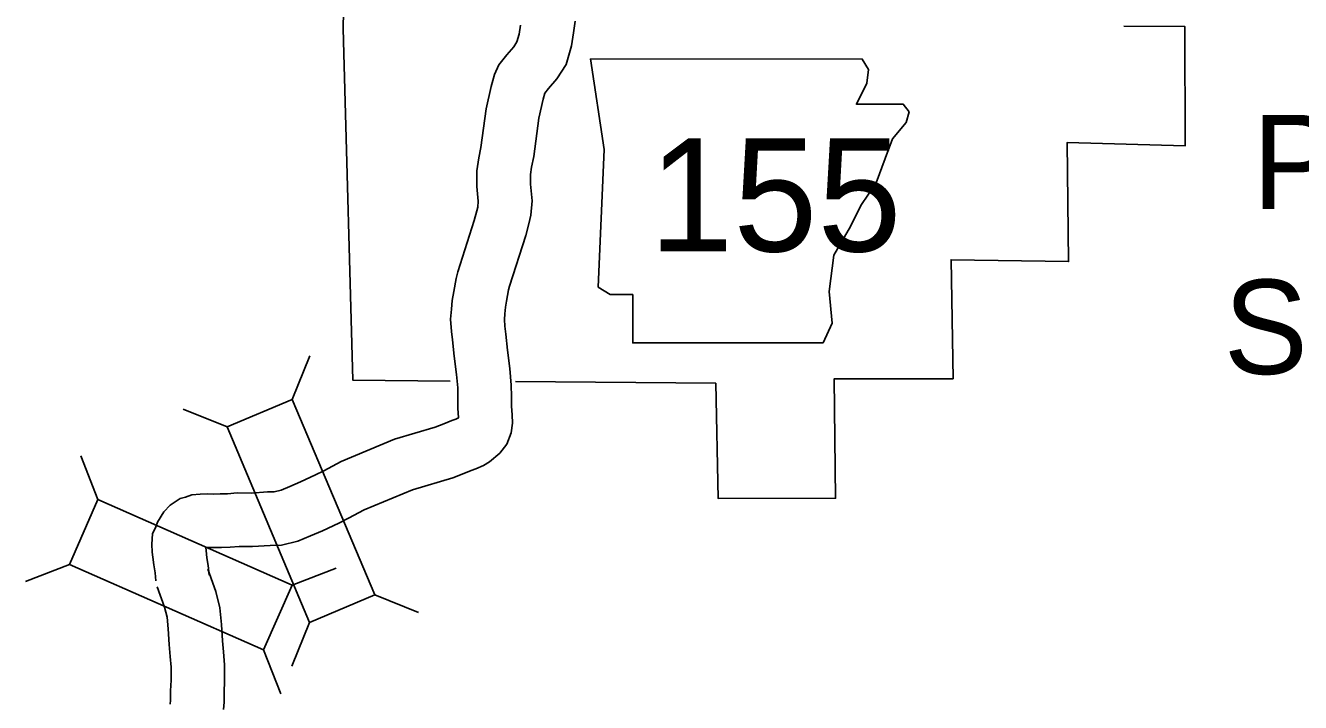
# Model space of a CAD drawing. Extents: x 1374139 to 1377472, y 1168351 to 1170484.
# Drawn here: x 1374780.3 to 1374851.7, y 1169701.5 to 1169739.4 of the extents above; entities that cross this region are included whole.
import ezdxf

# ---------------------------------------------------------------- set-up
doc = ezdxf.new("R2010")
doc.units = 0
doc.layers.add('Default', color=7, linetype='Continuous')

msp = doc.modelspace()

# ---------------------------------------------------------------- linework, layer by layer
at = {"layer": 'Default'}
for p, q in [((1374795.273, 1169718.442), (1374796.267, 1169720.888)), ((1374791.625, 1169716.902), (1374789.179, 1169717.896)), ((1374784.399, 1169712.832), (1374783.443, 1169715.293)), ((1374782.803, 1169709.208), (1374780.342, 1169708.252)), ((1374795.271, 1169708.045), (1374797.732, 1169709.001)), ((1374799.894, 1169707.498), (1374802.34, 1169706.504)), ((1374796.246, 1169705.958), (1374795.252, 1169703.512)), ((1374793.676, 1169704.421), (1374794.632, 1169701.96))]:
    msp.add_line(p, q, dxfattribs=at)
for points in [[(1374804.127, 1169719.47), (1374798.677, 1169719.513), (1374798.163, 1169737.81), (1374798.134, 1169739.222), (1374798.428, 1169754.193)], [(1374808.058, 1169739.411), (1374807.981, 1169738.902), (1374807.852, 1169738.464), (1374807.679, 1169738.198), (1374807.295, 1169737.746), (1374806.85, 1169737.177), (1374806.593, 1169736.648), (1374806.413, 1169735.965), (1374806.135, 1169734.716), (1374805.843, 1169732.557), (1374805.721, 1169731.981), (1374805.614, 1169731.253), (1374805.613, 1169730.361), (1374805.692, 1169729.54), (1374805.666, 1169729.217), (1374805.618, 1169729.003), (1374805.471, 1169728.47), (1374804.552, 1169725.596), (1374804.46, 1169725.208), (1374804.319, 1169724.484), (1374804.237, 1169723.992), (1374804.194, 1169723.493), (1374804.145, 1169722.935), (1374804.202, 1169722.242), (1374804.256, 1169721.785), (1374804.342, 1169720.863), (1374804.48, 1169719.839), (1374804.544, 1169719.102), (1374804.55, 1169718.579), (1374804.556, 1169717.957), (1374804.592, 1169717.413), (1374804.445, 1169717.347), (1374804.218, 1169717.267), (1374803.756, 1169717.074), (1374803.288, 1169716.889), (1374801.003, 1169716.215), (1374798.015, 1169714.969), (1374797.042, 1169714.449), (1374796.573, 1169714.212), (1374795.74, 1169713.82), (1374795.14, 1169713.567), (1374794.661, 1169713.368), (1374794.274, 1169713.275), (1374793.89, 1169713.265), (1374792.972, 1169713.202), (1374792.201, 1169713.212), (1374791.643, 1169713.166), (1374791.246, 1169713.156), (1374790.869, 1169713.146), (1374790.519, 1169713.157), (1374790.131, 1169713.146), (1374789.652, 1169713.092), (1374789.306, 1169712.962), (1374788.997, 1169712.887), (1374788.449, 1169712.519), (1374788.094, 1169712.144), (1374787.727, 1169711.579), (1374787.637, 1169711.317), (1374787.45, 1169710.915), (1374787.409, 1169710.338), (1374787.437, 1169709.895), (1374787.478, 1169709.619), (1374787.52, 1169709.189), (1374787.594, 1169708.733), (1374787.643, 1169708.282)], [(1374811.121, 1169739.631), (1374811.025, 1169738.97), (1374810.916, 1169738.251), (1374810.606, 1169737.196), (1374810.089, 1169736.401), (1374809.62, 1169735.85), (1374809.416, 1169735.589), (1374809.328, 1169735.256), (1374809.09, 1169734.188), (1374808.801, 1169732.044), (1374808.675, 1169731.452), (1374808.614, 1169731.033), (1374808.613, 1169730.503), (1374808.703, 1169729.565), (1374808.64, 1169728.764), (1374808.528, 1169728.273), (1374808.347, 1169727.615), (1374807.444, 1169724.792), (1374807.393, 1169724.575), (1374807.271, 1169723.951), (1374807.216, 1169723.617), (1374807.183, 1169723.233), (1374807.156, 1169722.927), (1374807.188, 1169722.54), (1374807.239, 1169722.099), (1374807.323, 1169721.203), (1374807.462, 1169720.17), (1374807.543, 1169719.249), (1374807.55, 1169718.611), (1374807.555, 1169718.07), (1374807.587, 1169717.578), (1374807.616, 1169717.108), (1374807.531, 1169716.581), (1374807.288, 1169715.945), (1374806.906, 1169715.439), (1374806.322, 1169714.941), (1374805.99, 1169714.752), (1374805.56, 1169714.558), (1374805.293, 1169714.465), (1374804.885, 1169714.294), (1374804.265, 1169714.05), (1374802.008, 1169713.383), (1374799.303, 1169712.256), (1374798.424, 1169711.786), (1374797.887, 1169711.515), (1374796.963, 1169711.08), (1374796.298, 1169710.799), (1374795.591, 1169710.506), (1374794.668, 1169710.284), (1374794.032, 1169710.268), (1374793.055, 1169710.201), (1374792.305, 1169710.211), (1374791.806, 1169710.169), (1374791.324, 1169710.157), (1374790.862, 1169710.144), (1374790.512, 1169710.155), (1374790.431, 1169710.153), (1374790.456, 1169709.986), (1374790.496, 1169709.576), (1374790.568, 1169709.135), (1374790.625, 1169708.607)], [(1374841.83, 1169739.345), (1374845.258, 1169739.326), (1374845.272, 1169732.645), (1374838.668, 1169732.832), (1374838.742, 1169726.163), (1374832.161, 1169726.261), (1374832.274, 1169719.603), (1374825.617, 1169719.588), (1374825.701, 1169712.909), (1374819.133, 1169712.887), (1374818.985, 1169719.354), (1374807.779, 1169719.442)], [(1374790.548, 1169708.946), (1374790.993, 1169707.691), (1374791.228, 1169706.771), (1374791.325, 1169705.833), (1374791.37, 1169704.922), (1374791.425, 1169704.311), (1374791.49, 1169703.576), (1374791.492, 1169702.66), (1374791.468, 1169702.059), (1374791.463, 1169701.498), (1374791.436, 1169701.084)], [(1374787.72, 1169707.943), (1374788.12, 1169706.816), (1374788.267, 1169706.243), (1374788.333, 1169705.603), (1374788.377, 1169704.713), (1374788.437, 1169704.046), (1374788.49, 1169703.441), (1374788.492, 1169702.715), (1374788.469, 1169702.133), (1374788.464, 1169701.611), (1374788.449, 1169701.383)]]:
    msp.add_lwpolyline(points, dxfattribs=at)
for points in [[(1374811.976, 1169737.512), (1374812.737, 1169732.436), (1374812.399, 1169724.739), (1374813.076, 1169724.316), (1374814.345, 1169724.316), (1374814.345, 1169721.609), (1374825.003, 1169721.609), (1374825.51, 1169722.709), (1374825.341, 1169724.485), (1374825.595, 1169726.515), (1374826.525, 1169728.122), (1374827.118, 1169729.307), (1374827.963, 1169730.575), (1374828.471, 1169731.929), (1374828.894, 1169733.029), (1374829.655, 1169733.959), (1374829.824, 1169734.551), (1374829.486, 1169734.974), (1374826.864, 1169734.974), (1374827.456, 1169736.158), (1374827.54, 1169736.92), (1374827.19, 1169737.504)], [(1374791.625, 1169716.902), (1374796.246, 1169705.958), (1374799.894, 1169707.498), (1374795.273, 1169718.442)], [(1374782.803, 1169709.208), (1374793.676, 1169704.421), (1374795.271, 1169708.045), (1374784.399, 1169712.832)]]:
    msp.add_lwpolyline(points, close=True, dxfattribs=at)

# ---------------------------------------------------------------- texts
for s, height, p in [('PETIT JEAN', 5.28, (1374849.032, 1169729.099)), ('155', 6.336, (1374815.258, 1169726.729)), ('STATE PARK', 5.28, (1374847.432, 1169719.869))]:
    msp.add_text(s, height=height, dxfattribs=at).set_placement(p)

doc.saveas('drawing.dxf')
